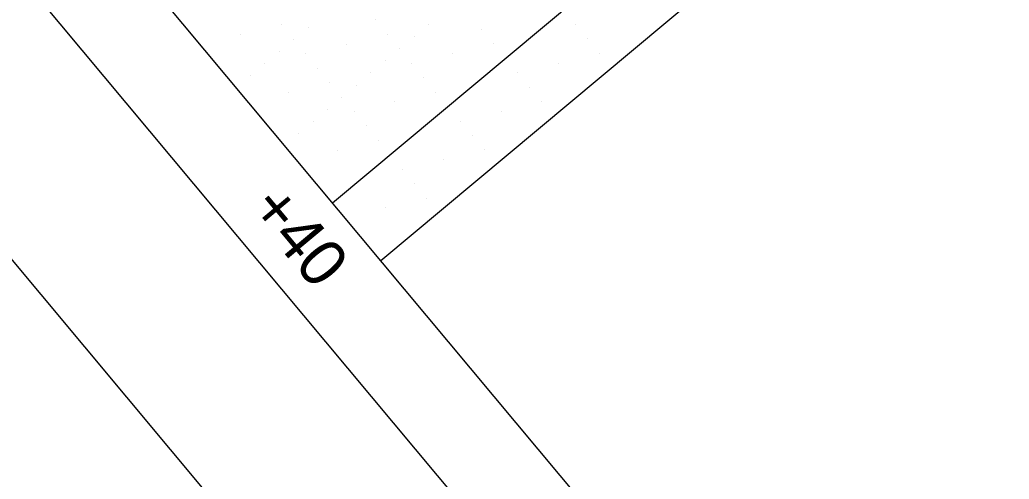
# Model space of a CAD drawing. Extents: x 2042995 to 2043795, y 305365 to 306249.
# Drawn here: x 2043306.5 to 2043359, y 305583.2 to 305607.7 of the extents above; entities that cross this region are included whole.
import ezdxf

# ---------------------------------------------------------------- set-up
doc = ezdxf.new("R2010")
doc.units = 0
for name, color, linetype in [('BR_BORDER LINES', 7, 'Continuous'), ('BR_CONCRETE', 7, 'Continuous'), ('BR_GRID DOTS', 7, 'Continuous'), ('BR_GRID LINES', 7, 'Continuous'), ('BR_TEXT', 7, 'Continuous'), ('RD_SHT_IplotShp', 7, 'Continuous')]:
    doc.layers.add(name, color=color, linetype=linetype)

msp = doc.modelspace()

# ---------------------------------------------------------------- linework, layer by layer
at = {"layer": 'BR_BORDER LINES'}
for p, q in [((2043026.498, 305945.211), (2043458.121, 305428.416)), ((2043041.019, 305935.624), (2043355.122, 305559.54)), ((2043360.173, 305623.692), (2043325.635, 305594.846))]:
    msp.add_line(p, q, dxfattribs=at)
at = {"layer": 'BR_CONCRETE'}
msp.add_spline([(2043139.109, 306017.548), (2043148.199, 306007.16), (2043160.233, 305993.368), (2043172.245, 305979.557), (2043184.234, 305965.727), (2043196.201, 305951.879), (2043208.145, 305938.012), (2043220.067, 305924.126), (2043231.966, 305910.221), (2043243.843, 305896.297), (2043255.698, 305882.355), (2043267.529, 305868.394), (2043279.339, 305854.414), (2043291.126, 305840.415), (2043302.89, 305826.398), (2043314.632, 305812.361), (2043326.352, 305798.306), (2043338.049, 305784.233), (2043349.724, 305770.14), (2043361.376, 305756.029), (2043373.005, 305741.899), (2043384.613, 305727.75), (2043396.197, 305713.582), (2043407.76, 305699.396), (2043419.299, 305685.191), (2043430.817, 305670.967), (2043442.311, 305656.724), (2043453.784, 305642.463), (2043465.234, 305628.182), (2043476.661, 305613.883), (2043488.066, 305599.566), (2043499.448, 305585.229), (2043510.808, 305570.874), (2043522.146, 305556.5), (2043533.461, 305542.107), (2043544.753, 305527.695), (2043547.219, 305524.543)], degree=3, dxfattribs=at)
at = {"layer": 'BR_GRID DOTS'}
for p, q in [((2043325.364, 305607.649), (2043325.364, 305607.649)), ((2043320.371, 305607.388), (2043320.371, 305607.388)), ((2043321.78, 305607.261), (2043321.78, 305607.261)), ((2043328.182, 305607.396), (2043328.182, 305607.396)), ((2043330.999, 305607.143), (2043330.999, 305607.143)), ((2043335.992, 305607.405), (2043335.992, 305607.405)), ((2043318.195, 305606.873), (2043318.195, 305606.873)), ((2043321.012, 305606.62), (2043321.012, 305606.62)), ((2043326.005, 305606.882), (2043326.005, 305606.882)), ((2043327.414, 305606.755), (2043327.414, 305606.755)), ((2043336.633, 305606.637), (2043336.633, 305606.637)), ((2043320.245, 305605.979), (2043320.245, 305605.979)), ((2043323.829, 305606.367), (2043323.829, 305606.367)), ((2043326.646, 305606.114), (2043326.646, 305606.114)), ((2043331.64, 305606.376), (2043331.64, 305606.376)), ((2043321.653, 305605.853), (2043321.653, 305605.853)), ((2043325.879, 305605.473), (2043325.879, 305605.473)), ((2043329.464, 305605.861), (2043329.464, 305605.861)), ((2043337.274, 305605.87), (2043337.274, 305605.87)), ((2043319.477, 305605.338), (2043319.477, 305605.338)), ((2043322.294, 305605.085), (2043322.294, 305605.085)), ((2043327.287, 305605.347), (2043327.287, 305605.347)), ((2043335.098, 305605.355), (2043335.098, 305605.355)), ((2043318.71, 305604.697), (2043318.71, 305604.697)), ((2043325.111, 305604.832), (2043325.111, 305604.832)), ((2043327.929, 305604.579), (2043327.929, 305604.579)), ((2043332.922, 305604.841), (2043332.922, 305604.841)), ((2043320.759, 305603.803), (2043320.759, 305603.803)), ((2043322.935, 305604.318), (2043322.935, 305604.318)), ((2043324.344, 305604.191), (2043324.344, 305604.191)), ((2043328.57, 305603.812), (2043328.57, 305603.812)), ((2043333.563, 305604.073), (2043333.563, 305604.073)), ((2043323.576, 305603.55), (2043323.576, 305603.55)), ((2043326.393, 305603.297), (2043326.393, 305603.297)), ((2043334.204, 305603.306), (2043334.204, 305603.306)), ((2043322.809, 305602.909), (2043322.809, 305602.909)), ((2043324.217, 305602.782), (2043324.217, 305602.782)), ((2043332.028, 305602.791), (2043332.028, 305602.791)), ((2043322.041, 305602.268), (2043322.041, 305602.268)), ((2043329.852, 305602.276), (2043329.852, 305602.276)), ((2043324.858, 305602.015), (2043324.858, 305602.015)), ((2043321.274, 305601.627), (2043321.274, 305601.627)), ((2043325.499, 305601.247), (2043325.499, 305601.247)), ((2043330.493, 305601.509), (2043330.493, 305601.509)), ((2043323.323, 305600.733), (2043323.323, 305600.733)), ((2043331.134, 305600.741), (2043331.134, 305600.741)), ((2043328.958, 305600.227), (2043328.958, 305600.227)), ((2043326.782, 305599.712), (2043326.782, 305599.712)), ((2043327.423, 305598.945), (2043327.423, 305598.945)), ((2043328.064, 305598.177), (2043328.064, 305598.177)), ((2043325.888, 305597.663), (2043325.888, 305597.663))]:
    msp.add_line(p, q, dxfattribs=at)
at = {"layer": 'BR_GRID LINES'}
msp.add_line((2043476.574, 305726.121), (2043323.07, 305597.916), dxfattribs=at)
at = {"layer": 'RD_SHT_IplotShp'}
msp.add_lwpolyline([(2043333.027, 306248.995), (2043794.566, 305696.382), (2043456.858, 305414.33), (2042995.319, 305966.944)], close=True, dxfattribs=at)

# ---------------------------------------------------------------- texts
at = {"layer": 'BR_TEXT'}
msp.add_text('+40', height=2.5, rotation=309.8684, dxfattribs=at).set_placement((2043318.545, 305597.583))

doc.saveas('drawing.dxf')
